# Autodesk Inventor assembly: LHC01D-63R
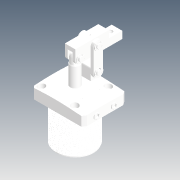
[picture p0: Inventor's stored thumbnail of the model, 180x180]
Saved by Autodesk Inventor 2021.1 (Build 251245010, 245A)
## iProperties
Created: 2019-04
Part Number: LHC01D-63R
Description: STEP AP214
Document SubType Name: Assembly
Designer: user
Title: LHC01D-63R.STEP
Revision Number: ÈÎºÎ
Sending System: SolidWorks 2016
Preprocessor: SwSTEP 2.0
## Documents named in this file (12)
- D:\Vault_2016\Projekty\Clamptek\Hydraulic\LHC01D\Inventor\LHC01D-63R\LHC01D-63R.iam
- D:\Vault_2016\Projekty\Clamptek\Hydraulic\LHC01D\Inventor\LHC01D-63R\CPLCU-50-08_4.ipt
- D:\Vault_2016\Projekty\Clamptek\Hydraulic\LHC01D\Inventor\LHC01D-63R\CPLCU-63-01_1.ipt
- D:\Vault_2016\Projekty\Clamptek\Hydraulic\LHC01D\Inventor\LHC01D-63R\CPLCU-63-02_1.ipt
- D:\Vault_2016\Projekty\Clamptek\Hydraulic\LHC01D\Inventor\LHC01D-63R\CPLCU-63-03_1.ipt
- D:\Vault_2016\Projekty\Clamptek\Hydraulic\LHC01D\Inventor\LHC01D-63R\CPLCU-63-04_1.ipt
- D:\Vault_2016\Projekty\Clamptek\Hydraulic\LHC01D\Inventor\LHC01D-63R\CPLCU-63-05_1.ipt
- D:\Vault_2016\Projekty\Clamptek\Hydraulic\LHC01D\Inventor\LHC01D-63R\LHC01D-63-07_1.ipt
- D:\Vault_2016\Projekty\Clamptek\Hydraulic\LHC01D\Inventor\LHC01D-63R\M4ningjin_9.ipt
- D:\Vault_2016\Projekty\Clamptek\Hydraulic\LHC01D\Inventor\LHC01D-63R\¶ÂÍ·_14.ipt
- D:\Vault_2016\Projekty\Clamptek\Hydraulic\LHC01D\Inventor\LHC01D-63R\LHC01D63»îÈû¸Ë.ipt
- D:\Vault_2016\Projekty\Clamptek\Hydraulic\LHC01D\Inventor\LHC01D-63R\LHC01D63R±¾Ìå.ipt
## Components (25 placed, 25 different names)
1. CPLCU-50-08_4_1
2. CPLCU-63-01_1_2
3. CPLCU-63-02_1_3
4. CPLCU-63-03_1_4
5. CPLCU-63-04_1_5
6. CPLCU-63-05_1_6
7. LHC01D-63-07_1_7
8. CPLCU-63-02_1_8
9. CPLCU-63-04_1_9
10. LHC01D-63-07_1_10
11. LHC01D-63-07_1_11
12. LHC01D-63-07_1_12
13. LHC01D-63-07_1_13
14. LHC01D-63-07_1_14
15. CPLCU-50-08_4_15
16. CPLCU-50-08_4_16
17. CPLCU-50-08_4_17
18. CPLCU-50-08_4_18
19. CPLCU-50-08_4_19
20. M4ningjin_9_20
21. ¶ÂÍ·_14_21
22. ¶ÂÍ·_14_22
23. M4ningjin_9_23
24. LHC01D63»îÈû¸Ë_24
25. LHC01D63R±¾Ìå_25
